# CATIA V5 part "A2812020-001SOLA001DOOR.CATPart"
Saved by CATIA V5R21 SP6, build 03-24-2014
Part number: A2812020-001SOLA001DOOR
Revision: --A
Definition: A2812020-001SOLA001.DOOR
Source: made
Description: START_SOLV5_EF2000______
Property "PTC_WM_NAME": "A2812020-001SOLA001.DOOR"
Property "PTC_WM_NUMBER": "A2812020-001SOLA001DOOR"
Property "PTC_WM_REVISION": "--A"
Property "PTC_WM_INIT_REV": "01"
Bounding box of the stored display mesh (mm): x -2 to 0, y -67.947 to 67.307, z 81.376 to 145.687
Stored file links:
  J:\Transfer\Fueller Werkstudent\Stellungen\A2812020-001SOLA001DOOR.CATPart
  C:\Temp\Catia\KonfigurationSample_02\___A2812010-001_SOL__A001.BOX_____________________.001-0-M_150225_HET.CATPart
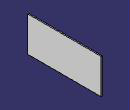
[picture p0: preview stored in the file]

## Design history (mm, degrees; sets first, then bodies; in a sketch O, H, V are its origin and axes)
AxisSystem1: origin (0, 0, 0), X (1, 0, 0), Y (0, 1, 0), Z (0, 0, 1)
Body1 (main body)
  Body2 "Positive"
    Sketch1 on yz-plane, origin (0, 0, 0), H (0, 1, 0), V (0, 0, 1)
      point P1 (-67.9471, 0)
      line L1 (67.3072, 81.3757) -> (67.3072, 145.6873)
      line L2 (67.3072, 145.6873) -> (-67.9471, 145.6873)
      line L3 (-67.9471, 145.6873) -> (-67.9471, 81.3757)
      line L4 (-67.9471, 81.3757) -> (67.3072, 81.3757)
      distance L1 V = 67.3072
      distance L3 V = 67.9471
      distance L4 H = 81.3757
      distance L2 H = 145.6873
      coincidence: P1 H, P1 L3
      horizontal: L2 H, L4 H
      vertical: L1 V, L3 V
    Pad1: profile Sketch1, direction (-1, 0, 0), length 2
  Assemble1: tool Body2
